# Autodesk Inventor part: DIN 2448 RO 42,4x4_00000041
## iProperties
Created: 2006-02
Part Number: DIN 2448 RO 42,4x4_00000041
Material: Default
Document SubType Name: Modeling
Designer: FranzK
Stock Number: DIN 2448 RO 42,4x4
Mass: 75.7986 g
Surface Area: 388.644 cm^2
Volume: 75.7986 cm^3
Density: 1 g/cm^3
G_L: 157.080 mm
G_W: 42.400 mm
G_H: 42.400 mm
AFG_Item: 42.4 x 4
CSToolsMass: 0.1
CSToolsVolume: 75799.0
CSToolsArea: 389.0
Author: FranzK
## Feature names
1. AFG_Detailed_DIN 2448 RO 42,4x4_00000041
2. AFG_Simplified_DIN 2448 RO 42,4x4_00000041
